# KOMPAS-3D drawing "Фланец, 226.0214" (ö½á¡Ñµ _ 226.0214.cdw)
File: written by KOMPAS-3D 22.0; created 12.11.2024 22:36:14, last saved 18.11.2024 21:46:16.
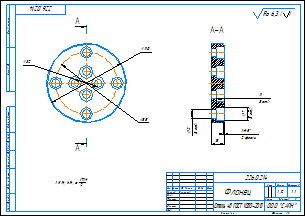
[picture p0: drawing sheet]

Sheet 1: A3, landscape

Document properties: Автор: aleksander.larionov.10@gmail.com; Знак неуказанной шероховатости: 4; Параметр неуказанной шероховатости: Ra 6,3; Масса: 1.122335; Полное имя файла: Фланец _ 226.0214.m3d

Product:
- Part/product: Фланец  | designation 226.0214
    Материал: Сталь 45 ГОСТ 1050-2013 (density 7810 kg/m3)
    Масса: 1.122335

Title block, sheet 1: Наименование: Фланец; designation: 226.0214; Материал: Сталь 45 ГОСТ 1050-2013; Масса: 1,12; Количество листов документа: 1; organisation: ООО "САЙН"; Форматы листов документа: A3; stored path: C:\Мои папки\Работа\Крышки, фланцы\226.0214\Фланец _ 226.0214.cdw; Разработал: Ларионов

Views: Вид 1, Сверху, Разрез А-А
Referenced files in C:\Мои папки\Работа\Крышки, фланцы\226.0214\: Фланец _ 226.0214.m3d
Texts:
  Ra 6,3
  Ra 6,3 ( )
Dimensions and other numbers on the sheet: 110; 85; 32; 1 H14, h14,    IT14 2 .; 226.0214; 18; 1; 2 фаски; 17; 8 отв.; 12; 11; 1:1; 1,12; 226.0214 Фланец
